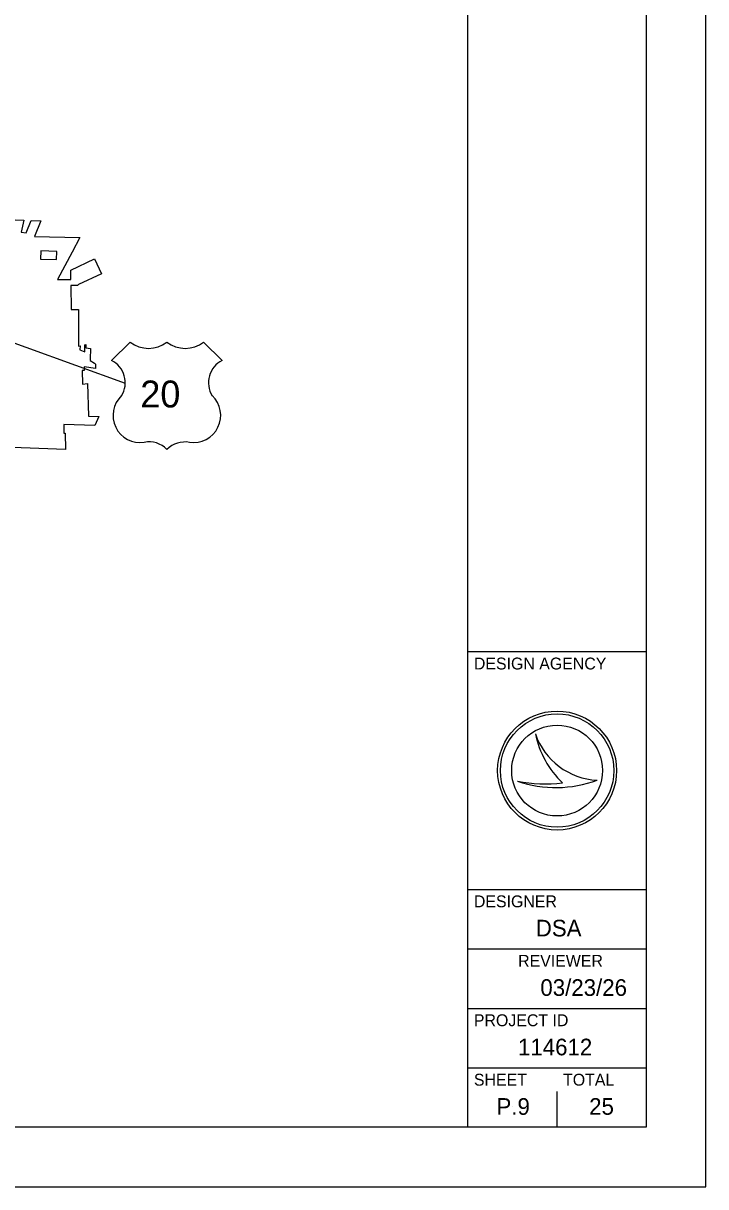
# Model space of a CAD drawing. Extents: x 0 to 798, y 0 to 440.
# Drawn here: x 565.2 to 680, y 0 to 195.7 of the extents above; entities that cross this region are included whole.
import ezdxf

# ---------------------------------------------------------------- set-up
doc = ezdxf.new("R2010")
doc.units = 0
for name, color, linetype in [('DV_X_Corp_Line', 7, 'Continuous'), ('GM_X_US_Route', 7, 'Continuous'), ('PV_P_Text', 7, 'Continuous'), ('SH_Border', 7, 'Continuous'), ('SH_Cut_Line', 7, 'Continuous'), ('SH_Data', 7, 'Continuous')]:
    doc.layers.add(name, color=color, linetype=linetype)

msp = doc.modelspace()

# ---------------------------------------------------------------- linework, layer by layer
at = {"layer": 'DV_X_Corp_Line'}
msp.add_lwpolyline([(560.83, 162.72), (565.31, 162.55), (564.85, 160.57), (565.7, 160.45), (566.53, 162.51), (568.14, 162.46), (567.07, 159.84), (574.71, 159.64), (573.42, 157.21), (570.94, 152.62), (573.2, 152.59), (573.18, 154.15), (577.2, 156.05), (578.37, 153.56), (574.5, 151.77), (574.3, 151.6), (573.2, 151.61), (573.27, 147.57), (574.5, 147.53), (574.51, 141.4), (574.78, 141.45), (574.74, 140.79), (575.58, 140.41), (575.58, 141.62), (575.7, 141.66), (575.7, 141.11), (576.09, 141.04), (576.49, 140.99), (576.47, 139.18), (576.47, 138.95), (577.17, 138.5), (577.35, 138.34), (577.37, 137.62), (575.44, 137.92), (575.44, 137.31), (575.13, 137.31), (575.14, 135), (576, 135.1), (576.16, 129.6), (577.9, 129.53), (577.26, 128.03), (572.01, 128.2), (572.05, 126.73), (572.25, 126.72), (572.33, 124.02), (561.88, 124.38)], dxfattribs=at)
msp.add_lwpolyline([(568.16, 157.39), (568.08, 156.02), (570.81, 155.93), (570.87, 157.29)], close=True, dxfattribs=at)
at = {"layer": 'GM_X_US_Route'}
msp.add_lwpolyline([(552.01, 146.14), (553.3, 145.67), (553.85, 145.47), (554.64, 145.19), (554.85, 145.11), (557.04, 144.32), (557.24, 144.24), (582.35, 135.13)], dxfattribs=at)
at = {"layer": 'PV_P_Text'}
for p, q in [((583.18, 142.08), (580.07, 138.97)), ((583.18, 142.08), (580.07, 138.97)), ((598.65, 138.97), (595.54, 142.08)), ((598.65, 138.97), (595.54, 142.08))]:
    msp.add_line(p, q, dxfattribs=at)
for centre, radius, start, end in [((586.27, 146.01), 5, 231.813, 308.187), ((586.27, 146.01), 5, 231.813, 308.187), ((592.45, 146.01), 5, 231.813, 308.187), ((592.45, 146.01), 5, 231.813, 308.187), ((578.12, 135.22), 4.23, 329.1175, 62.6108), ((578.12, 135.22), 4.23, 329.1175, 62.6108), ((600.59, 135.22), 4.23, 117.3892, 210.8825), ((600.59, 135.22), 4.23, 117.3892, 210.8825), ((584.86, 129.72), 4.56, 133.0046, 278.7282), ((584.86, 129.72), 4.56, 133.0046, 278.7282), ((593.85, 129.72), 4.56, 261.2718, 46.9954), ((593.85, 129.72), 4.56, 261.2718, 46.9954), ((586.39, 121.21), 4.08, 43.4177, 101.8742), ((586.39, 121.21), 4.08, 43.4177, 101.8742), ((592.41, 120.94), 4.33, 79.9613, 134.7468), ((592.41, 120.94), 4.33, 79.9613, 134.7468)]:
    msp.add_arc(centre, radius, start, end, dxfattribs=at)
at = {"layer": 'SH_Border'}
for p, q in [((640, 10), (640, 430)), ((640, 90), (670, 90)), ((640, 50), (670, 50)), ((640, 40), (670, 40)), ((640, 30), (670, 30)), ((640, 20), (670, 20))]:
    msp.add_line(p, q, dxfattribs=at)
msp.add_lwpolyline([(30, 430), (670, 430), (670, 10), (30, 10)], close=True, dxfattribs=at)
at = {"layer": 'SH_Cut_Line'}
msp.add_lwpolyline([(0, 0), (680, 0), (680, 440), (0, 440)], close=True, dxfattribs=at)
at = {"layer": 'SH_Data'}
for p, q in [((651.35, 76.19), (651.35, 76.19)), ((655, 70), (655, 70)), ((648.34, 68.19), (648.34, 68.19)), ((661.75, 68.37), (661.75, 68.37)), ((655, 10), (655, 16)), ((647.5, 13.5), (647.5, 13.5))]:
    msp.add_line(p, q, dxfattribs=at)
for radius in [10, 9.54, 9.54, 7.64]:
    msp.add_circle((655, 70), radius, dxfattribs=at)
for centre, radius, start, end in [((662.32, 79.95), 11.6, 198.9257, 198.9319), ((666.93, 79.4), 15.91, 191.6379, 191.6421), ((662.32, 79.95), 11.6, 198.9319, 267.1657), ((666.93, 79.4), 15.91, 191.6421, 226.0947), ((654.79, 87.4), 20.26, 251.4576, 290.0832), ((652.96, 93.09), 25.32, 259.4964, 259.4995), ((654.79, 87.4), 20.26, 251.4527, 251.4576), ((652.96, 93.09), 25.32, 259.4995, 276.6672)]:
    msp.add_arc(centre, radius, start, end, dxfattribs=at)

# ---------------------------------------------------------------- texts
at = {"layer": 'PV_P_Text'}
msp.add_text('20', height=4.528, dxfattribs=at).set_placement((584.89, 131.07))
at = {"layer": 'SH_Data'}
for s, height, p in [('DESIGN AGENCY', 2, (641, 87)), ('DESIGNER', 2, (641, 47)), ('DSA', 2.8, (651.41, 42.1)), ('REVIEWER', 2, (648.44, 37)), ('03/23/26', 2.8, (652.18, 32.1)), ('PROJECT ID', 2, (641, 27)), ('114612', 2.8, (648.42, 22.1)), ('SHEET', 2, (641, 17)), ('TOTAL', 2, (656, 17)), ('P.9', 2.8, (644.8, 12.1)), ('25', 2.8, (660.39, 12.1))]:
    msp.add_text(s, height=height, dxfattribs=at).set_placement(p)

doc.saveas('drawing.dxf')
